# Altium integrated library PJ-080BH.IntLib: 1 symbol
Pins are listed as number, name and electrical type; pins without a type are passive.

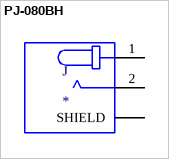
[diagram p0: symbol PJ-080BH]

## PJ-080BH
designator J
2.5 x 6.4 mm, 10.0 A, Horizontal, Through Hole, Shielded, Dc Power Jack Connector; MF: CUI Devices; MP: PJ-080BH
footprint CUI_PJ-080BH
pins: 1, 2, 3 SHIELD, 4 SHIELD, 5 SHIELD, 6 SHIELD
